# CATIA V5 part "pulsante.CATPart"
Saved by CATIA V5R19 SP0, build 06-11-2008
Part number: pulsante
Bounding box of the stored display mesh (mm): x 30.1 to 35.9, y -13 to -5, z -0.9 to 4.9
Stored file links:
  C:\Users\sisca\Desktop\HELTEC_CASE\pulsante.CATPart
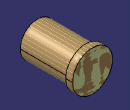
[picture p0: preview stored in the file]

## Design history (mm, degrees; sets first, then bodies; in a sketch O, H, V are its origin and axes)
Set1
  DatumSurface1
  DatumCurve1
  DatumCurve2
  DatumSurface2
  CLDGeom1 "Tessellation.1"
Body1 (main body)
  Sketch1 on face of DatumSurface1, origin (0, -5, 0), H (-1, 0, 0), V (0, 0, 1)
    circle A1 centre (-33, 2) radius 2.9
    reference projected circle E1 centre (-33, 2) radius 2.75 from edge of DatumCurve1
    radius A1 = 2.9
    concentricity: A1 E1
  Pad1: profile Sketch1, direction (0, -1, 0), length 1
  Sketch2 on end face of Pad1, origin (0, -6, 0), H (1, 0, 0), V (0, 0, 1)
    circle A1 centre (33, 2) radius 2.5
    reference projected circle E1 centre (33, 2) radius 2.75 from edge of DatumCurve2
    radius A1 = 2.5
    concentricity: A1 E1
  Pad2: profile Sketch2, direction (0, -1, 0), length 7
